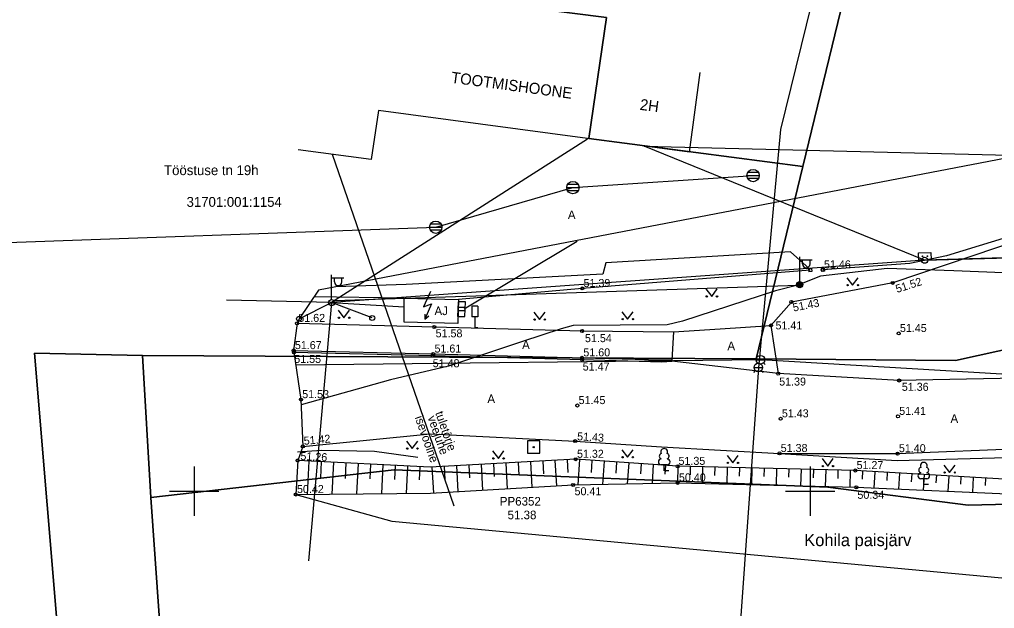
# Model space of a CAD drawing. Extents: x 542320 to 543602, y 6558748 to 6559969.
# Drawn here: x 542935.8 to 543015, y 6559790.5 to 6559838.3 of the extents above; entities that cross this region are included whole.
import ezdxf

# ---------------------------------------------------------------- set-up
doc = ezdxf.new("R2010")
doc.units = 0
for name, color, linetype in [('AED', 7, 'Continuous'), ('ALUSVORK', 7, 'Continuous'), ('ELRAJATISMP', 7, 'Continuous'), ('HALJASTUS', 7, 'Continuous'), ('HOONE', 7, 'Continuous'), ('KORGUS-EH2000', 7, 'Continuous'), ('LIIKLUS', 7, 'Continuous'), ('mootpiir', 7, 'Continuous'), ('MPKAABEL', 7, 'Continuous'), ('MPOHULIIN', 7, 'Continuous'), ('PIIR', 7, 'Continuous'), ('POST', 7, 'Continuous'), ('PUU', 7, 'Continuous'), ('RELJEEF', 7, 'Continuous'), ('SIOHULIIN', 7, 'Continuous'), ('SIRAJATIS', 7, 'Continuous'), ('SKKAEV', 7, 'Continuous'), ('SKTRASS', 7, 'Continuous'), ('TEE', 7, 'Continuous'), ('VEEKOGU', 7, 'Continuous'), ('VKAEV', 7, 'Continuous'), ('VORK', 7, 'Continuous'), ('VTRASS', 7, 'Continuous')]:
    doc.layers.add(name, color=color, linetype=linetype)

# ---------------------------------------------------------------- blocks, each defined once
blk = doc.blocks.new('VKORIS')
for p, q in [((0, 4), (0, -4)), ((-4, 0), (4, 0))]:
    blk.add_line(p, q)
blk = doc.blocks.new('KOHPP')
blk.add_lwpolyline([(1, 1), (-1, 1), (-1, -1), (1, -1)], close=True)
blk.add_circle((0, 0), 0.1)
blk = doc.blocks.new('VESIIB')
for p, q in [((-0.7, 0), (0.7, 0)), ((-0.49, -0.49), (-0.77, -0.77)), ((0.49, -0.49), (0.77, -0.77))]:
    blk.add_line(p, q)
blk.add_circle((0, 0), 0.7)
blk = doc.blocks.new('AJ')
for p, q in [((0.95, 4.49), (-0.19, 2.01)), ((-0.19, 2.01), (1.11, 2.46)), ((1.11, 2.46), (0, 0)), ((0, 0.79), (0, 0)), ((0, 0), (0.66, 0.53))]:
    blk.add_line(p, q)
blk = doc.blocks.new('MEPOST')
for radius in [0.5, 0.45, 0.4, 0.35, 0.3, 0.25, 0.2, 0.15, 0.1, 0.05]:
    blk.add_circle((0, 0), radius)
blk = doc.blocks.new('VAPOST')
for p, q in [((0, 0.5), (0, 4.5)), ((0, 4), (2, 4)), ((0.45, 3.36), (0.45, 4)), ((1.68, 3.36), (1.68, 4))]:
    blk.add_line(p, q)
blk.add_arc((1.07, 3.36), 0.613, 180, 0)
blk = doc.blocks.new('PUPOST')
blk.add_circle((0, 0), 0.5)
blk = doc.blocks.new('LEHTP1')
for p, q in [((0.48, 0.95), (-0.48, 0.95)), ((0, 0), (0, 0.95)), ((0.76, 0), (0, 0))]:
    blk.add_line(p, q)
for centre, radius, start, end in [((0, 3.04), 0.554, 332.5799, 207.4201), ((-0.47, 1.42), 0.475, 90.0016, 269.3953), ((-0.34, 2.35), 0.465, 109.0217, 253.1415), ((0.34, 2.35), 0.465, 286.8508, 70.9859), ((0.47, 1.42), 0.475, 270.6047, 89.9984)]:
    blk.add_arc(centre, radius, start, end)
blk = doc.blocks.new('LIIKLM')
for points in [[(-0.5, 3.5), (-0.5, 1.8)], [(0.5, 3.5), (-0.5, 3.5)], [(0.5, 3.5), (0.5, 1.8)], [(0.5, 1.8), (-0.5, 1.8)], [(0, 1.8), (0, 0)], [(0.5, 0), (0, 0)]]:
    blk.add_lwpolyline(points)
blk = doc.blocks.new('MURU')
for p, q in [((-0.93, 1.21), (0, 0)), ((0, 0), (0.89, 1.21))]:
    blk.add_line(p, q)
for centre in [(-0.8, 0), (0.86, 0)]:
    blk.add_circle(centre, 0.11)
blk = doc.blocks.new('REKAEV')
for p, q in [((-1, 0), (1, 0)), ((0.86, 0.5), (-0.86, 0.5)), ((0.86, -0.5), (-0.86, -0.5))]:
    blk.add_line(p, q)
blk.add_circle((0, 0), 1)
blk = doc.blocks.new('ELKAPP')
for p, q in [((1.19, 0.6), (-1.19, 0.6)), ((-1.19, 0.6), (-1.19, -0.6)), ((-0.27, 0.6), (-0.27, -0.6)), ((0.27, 0.6), (0.27, -0.6)), ((1.19, -0.6), (1.19, 0.6)), ((-1.19, -0.6), (1.19, -0.6))]:
    blk.add_line(p, q)
blk = doc.blocks.new('SIKAPP')
blk.add_lwpolyline([(-1, 0.6), (1, 0.6), (1, -0.6), (-1, -0.6)], close=True)
for centre, radius in [((-0.4, 0), 0.0608), ((-0.4, 0), 0.0581), ((-0.4, 0), 0.0553), ((-0.4, 0), 0.0526), ((-0.4, 0), 0.0499), ((-0.4, 0), 0.0472), ((-0.4, 0), 0.0444), ((-0.4, 0), 0.0417), ((-0.4, 0), 0.039), ((-0.4, 0), 0.0363), ((-0.4, 0), 0.0335), ((-0.4, 0), 0.0308), ((-0.4, 0), 0.0281), ((-0.4, 0), 0.0254), ((-0.4, 0), 0.0226), ((-0.4, 0), 0.0199), ((-0.4, 0), 0.0172), ((-0.4, 0), 0.0145), ((-0.4, 0), 0.0117), ((-0.4, 0), 0.00902), ((-0.4, 0), 0.0063), ((-0.4, 0), 0.00358), ((-0.4, 0), 0.000852), ((0.4, 0), 0.0608), ((0.4, 0), 0.0581), ((0.4, 0), 0.0553), ((0.4, 0), 0.0526), ((0.4, 0), 0.0499), ((0.4, 0), 0.0472), ((0.4, 0), 0.0444), ((0.4, 0), 0.0417), ((0.4, 0), 0.039), ((0.4, 0), 0.0363), ((0.4, 0), 0.0335), ((0.4, 0), 0.0308), ((0.4, 0), 0.0281), ((0.4, 0), 0.0254), ((0.4, 0), 0.0226), ((0.4, 0), 0.0199), ((0.4, 0), 0.0172), ((0.4, 0), 0.0145), ((0.4, 0), 0.0117), ((0.4, 0), 0.00902), ((0.4, 0), 0.0063), ((0.4, 0), 0.00358), ((0.4, 0), 0.000852)]:
    blk.add_circle(centre, radius)
blk = doc.blocks.new('RING02')
blk.add_circle((0, 0), 0.25)
blk = doc.blocks.new('TUPOST')
blk.add_circle((0, 0), 0.4)
blk = doc.blocks.new('VARPOS')
for p, q in [((-0.25, 0.25), (-0.25, -0.25)), ((-0.25, 0.25), (0.25, 0.25)), ((0.25, 0.25), (0.25, -0.25)), ((-0.25, -0.25), (0.25, -0.25))]:
    blk.add_line(p, q)

msp = doc.modelspace()

# ---------------------------------------------------------------- linework, layer by layer
at = {"layer": 'AED'}
for points in [[(543047.506, 6559830.252), (543031.229, 6559825.246), (543011.07, 6559819.081), (543008.098, 6559818.456), (543001.026, 6559817.957)], [(542999.997, 6559817.917), (542981.506, 6559816.443), (542971.468, 6559815.556)], [(542967.052, 6559815.668), (542959.715, 6559815.752)]]:
    msp.add_lwpolyline(points, dxfattribs=at)
at = {"layer": 'HOONE'}
for points in [[(542990.2, 6559827.491), (542991.068, 6559833.969)], [(542990.2, 6559827.491), (542964.953, 6559830.874), (542964.362, 6559826.918), (542958.429, 6559827.695)]]:
    msp.add_lwpolyline(points, dxfattribs=at)
msp.add_lwpolyline([(542967.033, 6559813.7), (542967.052, 6559815.668), (542971.468, 6559815.556), (542971.4, 6559813.596)], close=True, dxfattribs=at)
at = {"layer": 'LIIKLUS'}
msp.add_lwpolyline([(542958.377, 6559803.174), (542960.338, 6559803.329), (542964.627, 6559803.228), (542968.148, 6559802.757)], dxfattribs=at)
at = {"layer": 'mootpiir'}
msp.add_lwpolyline([(543090.147, 6559835.076), (543086.631, 6559835.669), (543046.075, 6559832.791), (542960.087, 6559816.316), (542958.508, 6559813.972), (542958.352, 6559813.615), (542958.072, 6559811.407), (542958.097, 6559811.262), (542958.667, 6559807.427), (542958.816, 6559803.633), (542958.4, 6559802.481), (542958.245, 6559799.726), (542966.032, 6559797.567), (543032.743, 6559791.379), (543093.076, 6559800.414), (543094.129, 6559807.466), (543092.769, 6559812.064), (543093.098, 6559815.823), (543092.736, 6559818.278), (543092.585, 6559819.369), (543092.195, 6559821.683), (543090.475, 6559823.796), (543090.459, 6559823.908), (543090.312, 6559826.089)], close=True, dxfattribs=at)
at = {"layer": 'MPKAABEL'}
msp.add_line((542961.419, 6559815.474), (542998.993, 6559816.701), dxfattribs=at)
msp.add_line((542961.419, 6559815.474), (542998.993, 6559816.701), dxfattribs=at)
for points in [[(543039.748, 6559819.685), (543038.588, 6559819.926), (543037.17, 6559820.01), (543030.258, 6559819.008), (543023.354, 6559817.818), (543020.365, 6559817.533), (543011.681, 6559817.864), (543006.243, 6559818.05), (543000.846, 6559817.433), (542998.993, 6559816.701), (542997.184, 6559816.239), (542989.641, 6559813.781), (542988.393, 6559813.49), (542980.759, 6559813.43), (542979.797, 6559813.172), (542976.647, 6559812.126), (542970.647, 6559810.142), (542965.94, 6559809.02), (542958.683, 6559807.008)], [(543039.748, 6559819.685), (543038.588, 6559819.926), (543037.17, 6559820.01), (543030.258, 6559819.008), (543023.354, 6559817.818), (543020.365, 6559817.533), (543011.681, 6559817.864), (543006.243, 6559818.05), (543000.846, 6559817.433), (542998.993, 6559816.701), (542997.184, 6559816.239), (542989.641, 6559813.781), (542988.393, 6559813.49), (542980.759, 6559813.43), (542979.797, 6559813.172), (542976.647, 6559812.126), (542970.647, 6559810.142), (542965.94, 6559809.02), (542958.683, 6559807.008)], [(542971.92, 6559814.798), (542981.092, 6559820.277)], [(542961.154, 6559815.297), (542967.038, 6559814.961)]]:
    msp.add_lwpolyline(points, dxfattribs=at)
at = {"layer": 'MPOHULIIN'}
for points in [[(542981.94, 6559828.56), (542961.154, 6559815.297), (542952.632, 6559815.492)], [(543065.505, 6559826.048), (543039.523, 6559819.62), (543009.299, 6559818.737), (542961.154, 6559815.297)], [(542961.154, 6559815.297), (542959.276, 6559794.355)]]:
    msp.add_lwpolyline(points, dxfattribs=at)
at = {"layer": 'PIIR'}
for points in [[(543002.19, 6559938.61), (542995.32, 6559882.88), (542984.27, 6559884.51), (542969.58, 6559880.67), (542959.71, 6559851.95), (542951.57, 6559852.97), (542950.23, 6559842.65), (542983.46, 6559838.42), (542982.04, 6559828.61), (542999.42, 6559826.35), (542995.62, 6559810.72), (542945.79, 6559811), (542937.03, 6559811.18), (542940.09, 6559774.59), (542939.23, 6559774.33), (542936.93, 6559773.44), (542936.99, 6559774.91), (542930.97, 6559773.19), (542914.12, 6559772.15), (542904.4, 6559772.44), (542898.6, 6559772.95), (542894.88, 6559773.72), (542892.18, 6559776.92)], [(542995.62, 6559810.72), (542999.42, 6559826.35), (543006.28, 6559854.63), (543022.96, 6559853.69), (543024.02, 6559863.81), (543009.03, 6559865.93), (543011.73, 6559877.03), (543035.19, 6559883.28), (543069.03, 6559887.03), (543076.83, 6559836.49), (543078.56, 6559825.31), (543011.79, 6559810.61), (542995.62, 6559810.72)], [(542950.23, 6559842.65), (542951.57, 6559852.97), (542959.71, 6559851.95), (542969.58, 6559880.67), (542984.27, 6559884.51), (542995.32, 6559882.88), (542994.65, 6559878.68), (543011.73, 6559877.03), (543009.03, 6559865.93), (543006.28, 6559854.63), (542999.42, 6559826.35), (542982.04, 6559828.61), (542983.46, 6559838.42), (542950.23, 6559842.65)], [(543110.35, 6559810.08), (543085.87, 6559802.96), (543074.33, 6559802.6), (543047.65, 6559805.6), (543029.51, 6559799.26), (543012.82, 6559798.86), (543001.44, 6559800.31), (542966.22, 6559801.72), (542946.49, 6559799.49), (542945.79, 6559811), (542995.62, 6559810.72), (543011.79, 6559810.61), (543078.56, 6559825.31), (543076.83, 6559836.49), (543087.22, 6559837.42), (543085.54, 6559829.09), (543128.04, 6559829.23)], [(542940.09, 6559774.59), (542937.03, 6559811.18), (542945.79, 6559811), (542946.49, 6559799.49), (542949.46, 6559757.36), (542949.37, 6559753.51), (542942.89, 6559752.66), (542939.23, 6559774.33), (542940.09, 6559774.59)], [(543023.83, 6559751.36), (543002.34, 6559750.46), (542985.84, 6559749.82), (542977.98, 6559750.87), (542965.4, 6559753.76), (542953.74, 6559755.74), (542949.46, 6559757.36), (542946.49, 6559799.49), (542966.22, 6559801.72), (543001.44, 6559800.31), (543012.82, 6559798.86), (543029.51, 6559799.26)]]:
    msp.add_lwpolyline(points, dxfattribs=at)
at = {"layer": 'POST'}
for points in [[(542958.508, 6559813.972), (542961.154, 6559815.297)], [(542964.454, 6559814.046), (542961.154, 6559815.297)]]:
    msp.add_lwpolyline(points, dxfattribs=at)
at = {"layer": 'RELJEEF'}
for points in [[(543092.769, 6559812.064), (543089.999, 6559809.142), (543084.85, 6559808.813), (543080.585, 6559810.073), (543073.543, 6559810.368), (543068.572, 6559810.695), (543059.132, 6559808.528), (543057.697, 6559808.874), (543055.711, 6559810.294), (543052.162, 6559811.058), (543042.149, 6559807.07), (543028.907, 6559800.786), (543017.173, 6559800.875), (543003.671, 6559801.671), (542989.215, 6559802.013), (542980.978, 6559802.587), (542969.167, 6559801.941), (542958.4, 6559802.481)], [(542959.317, 6559802.435), (542959.181, 6559799.735)], [(542960.315, 6559802.385), (542960.249, 6559801.065)], [(542961.314, 6559802.335), (542961.185, 6559799.756)], [(542976.293, 6559802.331), (542976.35, 6559801.29)], [(542977.292, 6559802.385), (542977.406, 6559800.307)], [(542978.29, 6559802.44), (542978.347, 6559801.402)], [(542979.289, 6559802.495), (542979.402, 6559800.421)], [(542980.288, 6559802.549), (542980.344, 6559801.514)], [(542981.286, 6559802.566), (542981.142, 6559800.507)], [(542982.283, 6559802.496), (542982.215, 6559801.512)], [(542983.281, 6559802.427), (542983.15, 6559800.548)], [(542984.278, 6559802.357), (542984.216, 6559801.463)], [(542962.313, 6559802.285), (542962.25, 6559801.025)], [(542963.311, 6559802.235), (542963.188, 6559799.776)], [(542964.31, 6559802.185), (542964.25, 6559800.985)], [(542965.309, 6559802.134), (542965.192, 6559799.796)], [(542966.308, 6559802.084), (542966.251, 6559800.945)], [(542967.306, 6559802.034), (542967.195, 6559799.817)], [(542968.305, 6559801.984), (542968.251, 6559800.906)], [(542969.304, 6559801.948), (542969.419, 6559799.85)], [(542970.302, 6559802.003), (542970.36, 6559800.955)], [(542971.301, 6559802.058), (542971.415, 6559799.964)], [(542972.299, 6559802.112), (542972.357, 6559801.067)], [(542973.298, 6559802.167), (542973.412, 6559800.078)], [(542974.296, 6559802.222), (542974.354, 6559801.178)], [(542975.295, 6559802.276), (542975.409, 6559800.193)], [(542985.276, 6559802.287), (542985.158, 6559800.589)], [(542986.274, 6559802.218), (542986.218, 6559801.413)], [(542987.271, 6559802.148), (542987.165, 6559800.629)], [(542988.269, 6559802.079), (542988.219, 6559801.364)], [(542989.266, 6559802.012), (542989.235, 6559800.672)], [(542990.266, 6559801.988), (542990.25, 6559801.318)], [(542991.266, 6559801.964), (542991.234, 6559800.622)], [(542992.266, 6559801.941), (542992.25, 6559801.269)], [(542993.265, 6559801.917), (542993.234, 6559800.572)], [(542994.265, 6559801.894), (542994.249, 6559801.22)], [(542995.265, 6559801.87), (542995.233, 6559800.522)], [(542996.265, 6559801.846), (542996.249, 6559801.172)], [(542997.264, 6559801.823), (542997.232, 6559800.472)], [(542998.264, 6559801.799), (542998.248, 6559801.123)], [(542999.264, 6559801.775), (542999.232, 6559800.422)], [(543000.263, 6559801.752), (543000.247, 6559801.074)], [(543001.263, 6559801.728), (543001.231, 6559800.372)], [(543002.263, 6559801.704), (543002.247, 6559801.026)], [(543003.263, 6559801.681), (543003.23, 6559800.322)], [(543004.261, 6559801.636), (543004.222, 6559800.963)], [(543005.26, 6559801.577), (543005.181, 6559800.247)], [(543006.258, 6559801.518), (543006.219, 6559800.861)], [(543007.256, 6559801.46), (543007.18, 6559800.162)], [(543008.254, 6559801.401), (543008.217, 6559800.76)], [(543009.253, 6559801.342), (543009.178, 6559800.076)], [(543010.251, 6559801.283), (543010.214, 6559800.658)], [(543011.249, 6559801.224), (543011.177, 6559799.99)], [(543012.248, 6559801.165), (543012.212, 6559800.556)], [(543013.246, 6559801.107), (543013.175, 6559799.904)], [(543014.244, 6559801.048), (543014.209, 6559800.454)]]:
    msp.add_lwpolyline(points, dxfattribs=at)
at = {"layer": 'SIOHULIIN'}
for points in [[(542986.521, 6559827.98), (543065.505, 6559826.048), (543087.322, 6559835.539)], [(543009.299, 6559818.737), (542986.521, 6559827.98)], [(543009.299, 6559818.737), (543039.532, 6559819.569)]]:
    msp.add_lwpolyline(points, dxfattribs=at)
at = {"layer": 'SKTRASS'}
msp.add_lwpolyline([(542931.797, 6559820.072), (542969.606, 6559821.415), (542980.749, 6559824.622), (542995.368, 6559825.605)], dxfattribs=at)
at = {"layer": 'TEE'}
for points in [[(543035.622, 6559817.731), (543034.167, 6559817.635), (543032.883, 6559817.779), (543032.269, 6559818.41), (543031.618, 6559821.447), (543030.542, 6559825.015), (543024.408, 6559822.902), (543015.216, 6559819.776), (543006.711, 6559816.894), (542998.482, 6559815.34), (542996.823, 6559813.441)], [(543060.355, 6559820.503), (543057.468, 6559819.65), (543048.685, 6559817.313), (543040.045, 6559814.486), (543035.967, 6559812.959), (543031.279, 6559811.296), (543026.934, 6559810.533), (543016.801, 6559809.157), (543007.227, 6559808.975), (542997.411, 6559809.534), (542988.775, 6559810.531)], [(542958.816, 6559803.633), (542969.162, 6559804.651), (542980.925, 6559804.056), (542987.926, 6559803.597), (542997.513, 6559803.059), (543007.107, 6559803.04), (543017.723, 6559803.474), (543028.051, 6559804.793), (543037.828, 6559808.06), (543042.163, 6559809.918), (543050.261, 6559812.635), (543059.043, 6559815.346), (543068.835, 6559817.386), (543079.318, 6559818.681), (543092.585, 6559819.369)], [(542999.997, 6559817.917), (542999.687, 6559818.268), (542998.416, 6559819.413), (542983.415, 6559818.525), (542983.184, 6559817.612), (542967.207, 6559816.754), (542961.486, 6559816.584)], [(542997.513, 6559803.059), (543007.066, 6559802.483), (543017.906, 6559802.775), (543028.213, 6559804.2), (543038.057, 6559807.69), (543042.598, 6559809.18), (543050.432, 6559811.965), (543059.255, 6559814.566), (543068.982, 6559816.272), (543079.524, 6559817.38), (543092.736, 6559818.278)], [(542958.352, 6559813.615), (542969.494, 6559813.316), (542981.487, 6559812.998), (542988.92, 6559812.912), (542988.783, 6559810.623)], [(542988.92, 6559812.912), (542992.705, 6559813.178), (542996.823, 6559813.441), (542997.411, 6559809.534)], [(542958.097, 6559811.262), (542969.375, 6559810.99), (542981.491, 6559810.667), (542987.972, 6559810.502), (542988.775, 6559810.531)], [(542958.1, 6559811.402), (542969.379, 6559811.13), (542981.495, 6559810.807), (542987.971, 6559810.642), (542988.77, 6559810.671)]]:
    msp.add_lwpolyline(points, dxfattribs=at)
at = {"layer": 'VEEKOGU'}
msp.add_lwpolyline([(542958.245, 6559799.726), (542969.193, 6559799.837), (542980.767, 6559800.499), (542989.253, 6559800.672), (543003.747, 6559800.309), (543017.23, 6559799.73), (543028.875, 6559799.639), (543042.762, 6559805.872), (543054.415, 6559808.402), (543057.212, 6559806.164), (543069.386, 6559808.821), (543079.867, 6559807.81), (543085.814, 6559807.064), (543094.129, 6559807.466)], dxfattribs=at)
at = {"layer": 'VTRASS'}
for points in [[(543002.613, 6559849.713), (542997.592, 6559829.35), (542995.798, 6559809.995), (542992.399, 6559762.213)], [(542961.193, 6559827.333), (542971.076, 6559798.794)], [(543084.909, 6559820.815), (543050.322, 6559816.388), (543018.303, 6559809.334), (542995.998, 6559810.646), (542958.256, 6559810.221)]]:
    msp.add_lwpolyline(points, dxfattribs=at)

# ---------------------------------------------------------------- block references
at = {"layer": 'AED', "xscale": 0.5, "yscale": 0.5, "rotation": -83.86232570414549}
for p in [(542999.997, 6559817.917), (543001.026, 6559817.957)]:
    msp.add_blockref('VARPOS', p, dxfattribs=at)
at = {"layer": 'ALUSVORK', "xscale": 0.5, "yscale": 0.5}
msp.add_blockref('KOHPP', (542977.561, 6559803.566), dxfattribs=at)
at = {"layer": 'ELRAJATISMP', "xscale": 0.49999999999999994, "yscale": 0.5000000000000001, "rotation": -92.020519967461}
msp.add_blockref('ELKAPP', (542971.7, 6559814.765), dxfattribs=at)
at = {"layer": 'HALJASTUS', "xscale": 0.5, "yscale": 0.5}
for p in [(543003.446, 6559816.709), (542992.011, 6559815.802), (542962.154, 6559814.063), (542978.034, 6559813.915), (542985.186, 6559813.952), (542967.699, 6559803.452), (542974.692, 6559802.655), (542985.179, 6559802.744), (542993.72, 6559802.289), (543001.432, 6559802.035), (543011.318, 6559801.511)]:
    msp.add_blockref('MURU', p, dxfattribs=at)
at = {"layer": 'HOONE', "xscale": 0.5, "yscale": 0.5}
msp.add_blockref('AJ', (542968.719, 6559813.959), dxfattribs=at)
at = {"layer": 'KORGUS-EH2000', "xscale": 0.5, "yscale": 0.5}
for p in [(543001.026, 6559817.957), (542981.506, 6559816.443), (543006.711, 6559816.894), (542998.482, 6559815.34), (542958.352, 6559813.615), (542969.494, 6559813.316), (542996.823, 6559813.441), (542981.487, 6559812.998), (543007.191, 6559812.792), (542958.072, 6559811.407), (542958.097, 6559811.262), (542969.375, 6559810.99), (542969.406, 6559811.127), (542981.491, 6559810.817), (542981.491, 6559810.667), (542997.411, 6559809.534), (543007.227, 6559808.975), (542958.667, 6559807.427), (542981.106, 6559806.944), (542997.606, 6559805.87), (543007.132, 6559806.068), (542980.925, 6559804.056), (542958.816, 6559803.633), (542997.513, 6559803.059), (543007.107, 6559803.04), (542958.4, 6559802.481), (542980.978, 6559802.587), (542989.253, 6559802.013), (543003.671, 6559801.671), (542989.253, 6559800.672), (542980.767, 6559800.499), (543003.747, 6559800.309), (542958.245, 6559799.726)]:
    msp.add_blockref('RING02', p, dxfattribs=at)
at = {"layer": 'LIIKLUS', "xscale": 0.5, "yscale": 0.5}
msp.add_blockref('LIIKLM', (542972.786, 6559813.248), dxfattribs=at)
at = {"layer": 'POST', "xscale": 0.5, "yscale": 0.5}
for name, p in [('VAPOST', (542999.158, 6559816.754)), ('PUPOST', (543009.299, 6559818.737)), ('VAPOST', (542961.154, 6559815.297)), ('MEPOST', (542999.158, 6559816.754)), ('PUPOST', (542961.154, 6559815.297)), ('TUPOST', (542964.454, 6559814.046)), ('TUPOST', (542958.508, 6559813.972))]:
    msp.add_blockref(name, p, dxfattribs=at)
at = {"layer": 'PUU', "xscale": 0.5, "yscale": 0.5}
for p in [(542988.155, 6559801.655), (543009.227, 6559800.528)]:
    msp.add_blockref('LEHTP1', p, dxfattribs=at)
at = {"layer": 'SIRAJATIS', "xscale": 0.5, "yscale": 0.5, "rotation": 1.4798891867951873}
msp.add_blockref('SIKAPP', (543009.32, 6559819.058), dxfattribs=at)
at = {"layer": 'SKKAEV', "xscale": 0.5, "yscale": 0.5}
for p in [(542995.368, 6559825.605), (542980.749, 6559824.622), (542969.606, 6559821.415)]:
    msp.add_blockref('REKAEV', p, dxfattribs=at)
at = {"layer": 'VKAEV', "xscale": 0.5, "yscale": 0.5}
for p in [(542995.795, 6559810.021), (542995.973, 6559810.663)]:
    msp.add_blockref('VESIIB', p, dxfattribs=at)
at = {"layer": 'VORK', "xscale": 0.5, "yscale": 0.5}
for p in [(542950, 6559800), (543000, 6559800)]:
    msp.add_blockref('VKORIS', p, dxfattribs=at)

# ---------------------------------------------------------------- texts
at = {"layer": 'ALUSVORK'}
for s, p in [('PP6352', (542974.809, 6559798.825)), ('51.38', (542975.439, 6559797.717))]:
    msp.add_text(s, height=0.7, dxfattribs=at).set_placement(p)
at = {"layer": 'HOONE'}
for s, p in [('TOOTMISHOONE', (542970.814, 6559833.14)), ('2H', (542986.138, 6559830.942))]:
    msp.add_text(s, height=0.9, rotation=352.36805, dxfattribs=at).set_placement(p)
msp.add_text('AJ', height=0.7, dxfattribs=at).set_placement((542969.506, 6559814.28))
at = {"layer": 'KORGUS-EH2000'}
for s, p in [('51.46', (543001.126, 6559818.074)), ('51.39', (542981.606, 6559816.56)), ('51.41', (542997.191, 6559813.121)), ('51.45', (543007.291, 6559812.909)), ('51.54', (542981.724, 6559812.086)), ('51.60', (542981.591, 6559810.934)), ('51.47', (542981.539, 6559809.78)), ('51.39', (542997.489, 6559808.565)), ('51.36', (543007.445, 6559808.137)), ('51.45', (542981.206, 6559807.061)), ('51.43', (542997.706, 6559805.987)), ('51.41', (543007.232, 6559806.185)), ('51.32', (542981.078, 6559802.704)), ('51.38', (542997.613, 6559803.176)), ('51.40', (543007.207, 6559803.157)), ('51.35', (542989.315, 6559802.13)), ('51.27', (543003.771, 6559801.788)), ('50.40', (542989.353, 6559800.789)), ('50.42', (542958.345, 6559799.843)), ('50.41', (542980.877, 6559799.662)), ('50.34', (543003.839, 6559799.375))]:
    msp.add_text(s, height=0.65, dxfattribs=at).set_placement(p)
for s, rotation, p in [('51.52', 17.66091, (543007.062, 6559816.076)), ('51.43', 11.0622, (542998.661, 6559814.565)), ('51.62', 359.87757, (542958.452, 6559813.732)), ('51.58', 359.87757, (542969.599, 6559812.482)), ('51.67', 359.87757, (542958.172, 6559811.524)), ('51.61', 359.87757, (542969.506, 6559811.244)), ('51.55', 359.87757, (542958.123, 6559810.401)), ('51.48', 359.87757, (542969.361, 6559810.054)), ('51.53', 359.87757, (542958.767, 6559807.544)), ('51.43', 356.43782, (542981.071, 6559804.13)), ('51.42', 5.22627, (542958.918, 6559803.75)), ('51.26', 356.97023, (542958.61, 6559802.531))]:
    msp.add_text(s, height=0.65, rotation=rotation, dxfattribs=at).set_placement(p)
at = {"layer": 'PIIR'}
for s, p in [('Tööstuse tn 19h', (542947.552, 6559825.639)), ('31701:001:1154', (542949.379, 6559823.065))]:
    msp.add_text(s, height=0.8, dxfattribs=at).set_placement(p)
at = {"layer": 'TEE'}
for p in [(542980.334, 6559822.067), (542976.618, 6559811.522), (542993.285, 6559811.431), (542973.8, 6559807.144), (543011.395, 6559805.537)]:
    msp.add_text('A', height=0.7, dxfattribs=at).set_placement(p)
at = {"layer": 'VEEKOGU'}
msp.add_text('Kohila paisjärv', height=1, dxfattribs=at).set_placement((542999.523, 6559795.533))
at = {"layer": 'VTRASS'}
for s, p in [('tuletõrje', (542969.555, 6559806.34)), ('isevoolne ', (542967.902, 6559805.978)), ('veejuhe', (542968.935, 6559805.978))]:
    msp.add_text(s, height=0.7, rotation=289.18055, dxfattribs=at).set_placement(p)

doc.saveas('drawing.dxf')
